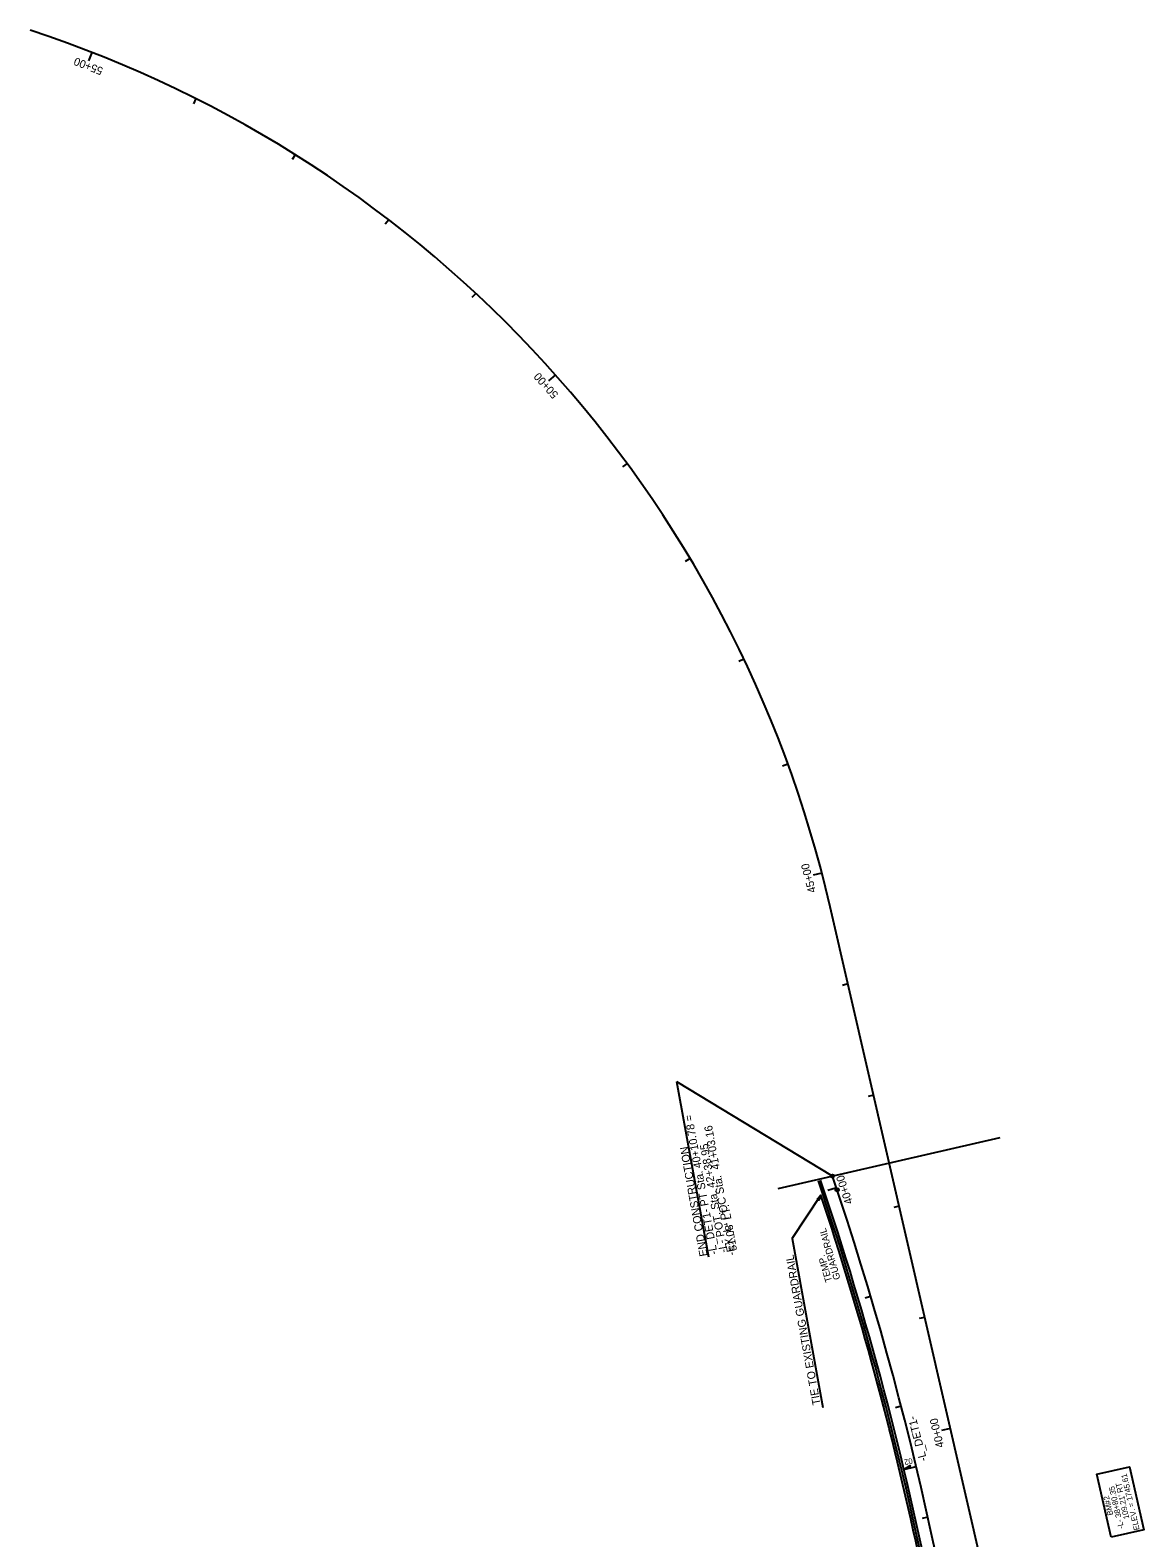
# Model space of a CAD drawing. Extents: x 473658 to 481584, y 489119 to 506230.
# Drawn here: x 480487 to 481464, y 491971 to 493294 of the extents above; entities that cross this region are included whole.
import ezdxf

# ---------------------------------------------------------------- set-up
doc = ezdxf.new("R2010")
doc.units = 0
for name, color, linetype in [('Default', 7, 'Continuous'), ('Exist Horizontal Alignment', 7, 'Continuous'), ('Prop Dimension', 7, 'Continuous'), ('Prop EOT', 7, 'Continuous'), ('Prop Grid Mask', 7, 'Continuous'), ('Prop Guardrail', 7, 'Continuous'), ('Prop Horizontal Alignment', 7, 'Continuous'), ('Prop Horizontal Alignment Direction Label', 7, 'Continuous'), ('Prop Horizontal Alignment Station Label', 7, 'Continuous'), ('Prop Horizontal Alignment Tick Label', 7, 'Continuous'), ('Prop Horizontal Alignment Tick Large', 7, 'Continuous'), ('Prop Horizontal Alignment Tick Small', 7, 'Continuous'), ('Prop Paved Shoulder', 7, 'Continuous'), ('Prop Superelevation  Arrow CELL', 7, 'Continuous'), ('Prop Superelevation Label', 7, 'Continuous'), ('Scratch_Level_1', 7, 'Continuous'), ('Scratch_Level_9', 7, 'Continuous'), ('Sheet Profile Grid Major CELL', 7, 'Continuous')]:
    doc.layers.add(name, color=color, linetype=linetype)

msp = doc.modelspace()

# ---------------------------------------------------------------- linework, layer by layer
at = {"layer": 'Exist Horizontal Alignment'}
msp.add_lwpolyline([(481177.5, 492268.5), (481180.7, 492271.8), (481178.8, 492267.6), (481178.5, 492268.5)], close=True, dxfattribs=at)
at = {"layer": 'Prop Dimension'}
for q in [(481180.7, 492271.8), (481182.4, 492085.7)]:
    msp.add_line((481155.5, 492233.8), q, dxfattribs=at)
at = {"layer": 'Prop EOT'}
msp.add_arc((478448.7, 491360.3), 2884, 11.0687, 18.704, dxfattribs=at)
at = {"layer": 'Prop Grid Mask'}
msp.add_lwpolyline([(481435.3, 491971.9), (481422.6, 492027.1), (481451.2, 492033.6), (481463.9, 491978.5)], close=True, dxfattribs=at)
at = {"layer": 'Prop Guardrail'}
msp.add_arc((478448.7, 491360.3), 2880, 11.9855, 18.4511, dxfattribs=at)
at = {"layer": 'Prop Horizontal Alignment'}
msp.add_line((481374.8, 491717.8), (481188.8, 492524.8), dxfattribs=at)
for centre, radius, start, end in [((480155.9, 492286.7), 1060, 12.9811, 71.7884), ((478448.7, 491360.3), 2895, 353.0365, 18.704)]:
    msp.add_arc(centre, radius, start, end, dxfattribs=at)
at = {"layer": 'Prop Horizontal Alignment Station Label'}
for p in [(481082.4, 492217.4), (481190.8, 492288.6)]:
    msp.add_line(p, (481054.4, 492371.2), dxfattribs=at)
for centre in [(481190.8, 492288.6), (481194.9, 492276.6)]:
    msp.add_circle(centre, 1.5, dxfattribs=at)
at = {"layer": 'Prop Horizontal Alignment Tick Large'}
for p, q in [((480541.2, 493274.1), (480538.3, 493266.7)), ((480947.9, 492991.2), (480941.9, 492985.9)), ((481181.5, 492554.4), (481173.8, 492552.4)), ((481194.2, 492278.4), (481186.7, 492275.9)), ((481294.3, 492067.3), (481286.5, 492065.5))]:
    msp.add_line(p, q, dxfattribs=at)
at = {"layer": 'Prop Horizontal Alignment Tick Small'}
for p, q in [((480632.5, 493233.5), (480630.3, 493229)), ((480719.6, 493184.3), (480717, 493180.1)), ((480801.7, 493127.2), (480798.6, 493123.3)), ((480878, 493062.7), (480874.6, 493059)), ((481010.7, 492913.5), (481006.7, 492910.5)), ((481066, 492830.2), (481061.7, 492827.6)), ((481113.1, 492742), (481108.6, 492739.9)), ((481151.7, 492649.8), (481147, 492648.1)), ((481204.4, 492457.1), (481199.5, 492455.9)), ((481226.9, 492359.6), (481222, 492358.5)), ((481249.3, 492262.2), (481244.5, 492261)), ((481224.3, 492183.1), (481219.5, 492181.6)), ((481271.8, 492164.7), (481266.9, 492163.6)), ((481251.1, 492086.7), (481246.2, 492085.5)), ((481274.5, 491989.5), (481269.6, 491988.4))]:
    msp.add_line(p, q, dxfattribs=at)
at = {"layer": 'Prop Paved Shoulder'}
msp.add_arc((478448.7, 491360.3), 2882, 10.9492, 18.704, dxfattribs=at)
at = {"layer": 'Prop Superelevation  Arrow CELL'}
msp.add_lwpolyline([(481253.5, 492031.4), (481258.9, 492034.7), (481258, 492032.5)], close=True, dxfattribs=at)
at = {"layer": 'Prop Superelevation Label'}
msp.add_line((481253.5, 492031.4), (481264.2, 492033.9), dxfattribs=at)
at = {"layer": 'Scratch_Level_9'}
for p, q in [((481143.1, 492277.7), (481338, 492322.6)), ((481190.8, 492288.6), (481190.8, 492288.6)), ((481190.8, 492288.6), (481190.8, 492288.6)), ((481190.8, 492288.6), (481190.8, 492288.6))]:
    msp.add_line(p, q, dxfattribs=at)

# ---------------------------------------------------------------- texts
at = {"layer": 'Default'}
for s, p in [('ELEV. = 1745.61', (481460.2, 491978.6)), ('BM#2', (481437.1, 491991.6)), ('-L- 38+80.35', (481446.5, 491979.9)), ("109.21' RT", (481451.2, 491988.5))]:
    msp.add_text(s, height=5, rotation=102.9811, dxfattribs=at).set_placement(p)
at = {"layer": 'Prop Horizontal Alignment Direction Label'}
msp.add_text('-L_DET1-', height=7, rotation=104.4167, dxfattribs=at).set_placement((481273.8, 492039.4))
at = {"layer": 'Prop Horizontal Alignment Station Label'}
for s, p in [('-L_DET1- PT Sta. 40+10.78 =', (481090, 492220.4)), ('END CONSTRUCTION            ', (481081.3, 492218.8)), ('-L- POT. Sta. 42+38.95', (481098.6, 492222)), ("51.08' LT.     ", (481107.2, 492223.5))]:
    msp.add_text(s, height=7, rotation=100.2943, dxfattribs=at).set_placement(p)
at = {"layer": 'Prop Horizontal Alignment Tick Label'}
for s, rotation, p in [('55+00', 158.6824, (480551.7, 493260.4)), ('50+00', 131.6561, (480950.9, 492974.3)), ('45+00', 104.6298, (481176.5, 492538)), ('40+00', 108.4907, (481208.8, 492265.2)), ('40+00', 102.9811, (481288.7, 492051.2))]:
    msp.add_text(s, height=7, rotation=rotation, dxfattribs=at).set_placement(p)
at = {"layer": 'Prop Superelevation Label'}
msp.add_text('.02', height=5, rotation=193.456, dxfattribs=at).set_placement((481262.3, 492042))
at = {"layer": 'Scratch_Level_1'}
msp.add_text('-EX_L- POC Sta.  41+03.16', height=7, rotation=100.2943, dxfattribs=at).set_placement((481105.8, 492219.6))
at = {"layer": 'Sheet Profile Grid Major CELL'}
for s, height, rotation, p in [('GUARDRAIL', 6, 106.1357, (481197.9, 492198.6)), ('TIE TO EXISTING GUARDRAIL', 7, 100.2943, (481180.4, 492088.5)), ('TEMP.', 6, 106.1357, (481190.6, 492196.5))]:
    msp.add_text(s, height=height, rotation=rotation, dxfattribs=at).set_placement(p)

doc.saveas('drawing.dxf')
